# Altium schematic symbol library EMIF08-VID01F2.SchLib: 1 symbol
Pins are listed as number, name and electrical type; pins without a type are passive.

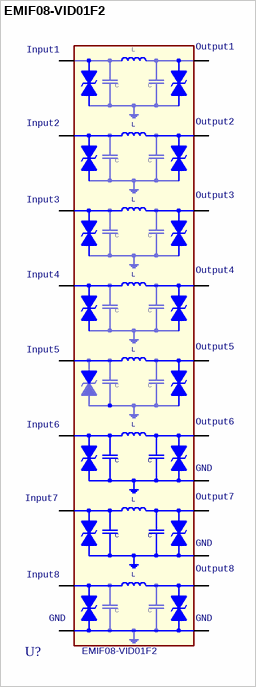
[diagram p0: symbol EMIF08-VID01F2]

## EMIF08-VID01F2
designator U?
footprint ST_CSP20N43P3X12_392X129X65
pins: A1 Input1, A3 Input2, A4 Input3, A6 Input4, A7 Input5, A9 Input6, A10 Input7, A12 Input8, B2 GND, B5 GND1, B8 GND2, B11 GND3, C1 Output1, C3 Output2, C4 Output3, C6 Output4, C7 Output5, C9 Output6, C10 Output7, C12 Output8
